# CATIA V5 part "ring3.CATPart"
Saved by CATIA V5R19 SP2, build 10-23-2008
Part number: ring3
Bounding box of the stored display mesh (mm): x 1208.801 to 1608.814, y 0 to 783.497, z 0 to 414.335
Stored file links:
  C:\BEHROOZ\catia learning\tarh haye mashin\hb\ring3.CATPart
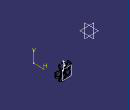
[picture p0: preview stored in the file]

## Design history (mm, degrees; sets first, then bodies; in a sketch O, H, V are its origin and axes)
Body1 (main body)
  Plane1: stored without definition
  DatumCurve1
  Line1: stored without definition
  Sketch1 on Plane1, origin (1402.6545, 0, 0), H (0, 1, 0), V (0, 0, 1)
    line L1 (763.5635, 414.3348) -> (783.4975, 338.6087)
    axis line L2 (763.5635, 208.175) -> (934.6232, 208.175)
    arc A1 centre (2119.5521, -103.7831) radius 1407.392 from (783.4975, 338.6087) to (747.1693, 208.175) ccw
    line L3 (747.1693, 208.175) -> (738.3224, 208.175)
    arc A2 centre (1438.5484, 90.6387) radius 710.022 from (738.3224, 208.175) to (762.752, 308.4239) cw
    line L4 (761.4882, 368.214) -> (744.4421, 414.3348)
    line L5 (744.4421, 414.3348) -> (763.5635, 414.3348)
    arc A3 centre (675.6576, 336.4913) radius 91.5053 from (762.752, 308.4239) to (761.4882, 368.214) ccw
  Shaft1: profile Sketch1, axis Line1, angle 360
  Plane2: stored without definition
  Plane3: type Offset, RefPlane Plane2, Offset 85
  Sketch2 on Plane3, origin (0, 841, 0), H (-1, 0, 0), V (0, 0, 1)
    construction line L1 (-1402.6545, 208.175) -> (-1196.4947, 208.175)
    construction line L2 (-1402.6545, 208.175) -> (-1338.9476, 404.2446)
    construction line L3 (-1402.6545, 208.175) -> (-1569.4414, 329.3527)
    construction line L4 (-1402.6545, 208.175) -> (-1569.4414, 86.9972)
    construction line L5 (-1402.6545, 208.175) -> (-1338.9476, 12.1053)
    axis line L6 through (-1402.6545, 208.175) direction (-0.309, 0.9511)
    line L7 (-1425.7363, 229.4708) -> (-1503.5268, 285.9888)
    arc A1 centre (-1282.5124, 371.6811) radius 238.7047 from (-1507.0557, 290.6859) to (-1521.217, 371.549) cw
    line L8 (-1396.4983, 238.9708) -> (-1366.785, 330.4189)
    arc A2 centre (-1595.9581, 269.8364) radius 238.7047 from (-1366.691, 336.2931) to (-1402.7643, 410.0366) ccw
    arc A3 centre (-1402.6545, 208.175) radius 190.3856 from (-1441.2397, 394.6095) to (-1481.022, 381.6835) ccw
    arc A4 centre (-1402.6545, 208.175) radius 206.1598 from (-1338.9476, 404.2446) to (-1411.276, 414.1545) ccw
    point P15 (-1338.9476, 404.2446)
    arc A5 centre (-1402.6545, 208.175) radius 206.1598 from (-1516.7514, 379.8834) to (-1569.4414, 329.3527) ccw
    point P16 (-1569.4414, 329.3527)
    arc A6 centre (-1201.2324, 325.4245) radius 294.2074 from (-1492.5962, 366.2304) to (-1495.1281, 311.8856) ccw
    arc A7 centre (-1246.5155, 716.3226) radius 483.7877 from (-1485.0087, 295.405) to (-1437.1395, 271.6732) ccw
    arc A8 centre (-1634.526, 184.6389) radius 294.2074 from (-1422.7928, 388.9108) to (-1388.8015, 346.4332) cw
    arc A9 centre (-1827.6553, 527.4988) radius 483.7877 from (-1387.3012, 327.1521) to (-1412.0789, 279.8159) cw
    arc A10 centre (-1511.217, 371.5545) radius 10 from (-1521.217, 371.549) to (-1516.7514, 379.8834) cw
    arc A11 centre (-1410.8578, 404.1632) radius 10 from (-1402.7643, 410.0366) to (-1411.276, 414.1545) ccw
    arc A12 centre (-1429.2591, 290.0552) radius 20 from (-1437.1395, 271.6732) to (-1412.0789, 279.8159) ccw
    arc A13 centre (-1405.5056, 335.4346) radius 20 from (-1387.3012, 327.1521) to (-1388.8015, 346.4332) ccw
    arc A14 centre (-1475.1493, 312.806) radius 20 from (-1485.0087, 295.405) to (-1495.1281, 311.8856) cw
    arc A15 centre (-1472.7895, 363.4564) radius 20 from (-1492.5962, 366.2304) to (-1481.022, 381.6835) cw
    arc A16 centre (-1437.1863, 375.0246) radius 20 from (-1441.2397, 394.6095) to (-1422.7928, 388.9108) cw
    arc A17 centre (-1376.2956, 333.5091) radius 10 from (-1366.785, 330.4189) to (-1366.691, 336.2931) ccw
    arc A18 centre (-1497.6489, 294.079) radius 10 from (-1503.5268, 285.9888) to (-1507.0557, 290.6859) cw
    point P48 (-1569.4414, 329.3527)
    point P49 (-1569.4414, 86.9972)
    point P51 (-1569.4414, 329.3527)
    point P52 (-1569.4414, 86.9972)
    line L9 (-1430.0407, 192.8036) -> (-1507.8312, 136.2856)
    arc A19 centre (-1521.0321, 372.9631) radius 238.7047 from (-1513.3888, 134.3809) to (-1594.6703, 145.9007) cw
    line L10 (-1430.0407, 223.5463) -> (-1507.8312, 280.0643)
    arc A20 centre (-1521.0321, 43.3868) radius 238.7047 from (-1513.3888, 281.969) to (-1594.6703, 270.4492) ccw
    arc A21 centre (-1402.6545, 208.175) radius 190.3856 from (-1591.8878, 229.0898) to (-1591.8878, 187.2602) ccw
    arc A22 centre (-1402.6545, 208.175) radius 206.1598 from (-1569.4414, 329.3527) to (-1601.2168, 263.6267) ccw
    arc A23 centre (-1402.6545, 208.175) radius 206.1598 from (-1601.2168, 152.7232) to (-1569.4414, 86.9972) ccw
    arc A24 centre (-1451.9226, 435.9709) radius 294.2074 from (-1580.7677, 171.4772) to (-1529.8651, 152.2757) ccw
    arc A25 centre (-1837.6821, 513.6982) radius 483.7877 from (-1511.0641, 156.8071) to (-1473.7014, 194.9998) ccw
    arc A26 centre (-1451.9226, -19.621) radius 294.2074 from (-1580.7677, 244.8727) to (-1529.8651, 264.0742) cw
    arc A27 centre (-1837.6821, -97.3483) radius 483.7877 from (-1511.0641, 259.5428) to (-1473.7014, 221.3501) cw
    arc A28 centre (-1591.5854, 155.413) radius 10 from (-1594.6703, 145.9007) to (-1601.2168, 152.7232) cw
    arc A29 centre (-1591.5854, 260.9369) radius 10 from (-1594.6703, 270.4492) to (-1601.2168, 263.6267) ccw
    arc A30 centre (-1488.7486, 208.175) radius 20 from (-1473.7014, 194.9998) to (-1473.7014, 221.3501) ccw
    arc A31 centre (-1524.5667, 244.7888) radius 20 from (-1511.0641, 259.5428) to (-1529.8651, 264.0742) ccw
    arc A32 centre (-1524.5667, 171.5611) radius 20 from (-1511.0641, 156.8071) to (-1529.8651, 152.2757) cw
    arc A33 centre (-1572.0089, 189.4573) radius 20 from (-1580.7677, 171.4772) to (-1591.8878, 187.2602) cw
    arc A34 centre (-1572.0089, 226.8927) radius 20 from (-1591.8878, 229.0898) to (-1580.7677, 244.8727) cw
    arc A35 centre (-1513.709, 271.9742) radius 10 from (-1507.8312, 280.0643) to (-1513.3888, 281.969) ccw
    arc A36 centre (-1513.709, 144.3757) radius 10 from (-1507.8312, 136.2856) to (-1513.3888, 134.3809) cw
    point P85 (-1569.4414, 86.9972)
    point P86 (-1338.9476, 12.1053)
    point P88 (-1569.4414, 86.9972)
    point P89 (-1338.9476, 12.1053)
    line L11 (-1396.4983, 177.3792) -> (-1366.785, 85.931)
    arc A37 centre (-1595.9581, 146.5135) radius 238.7047 from (-1366.691, 80.0568) to (-1402.7643, 6.3133) cw
    line L12 (-1425.7363, 186.8792) -> (-1503.5268, 130.3611)
    arc A38 centre (-1282.5124, 44.6688) radius 238.7047 from (-1507.0557, 125.664) to (-1521.217, 44.8009) ccw
    arc A39 centre (-1402.6545, 208.175) radius 190.3856 from (-1481.022, 34.6664) to (-1441.2397, 21.7404) ccw
    arc A40 centre (-1402.6545, 208.175) radius 206.1598 from (-1569.4414, 86.9972) to (-1516.7514, 36.4665) ccw
    arc A41 centre (-1402.6545, 208.175) radius 206.1598 from (-1411.276, 2.1955) to (-1338.9476, 12.1053) ccw
    arc A42 centre (-1634.526, 231.7111) radius 294.2074 from (-1422.7928, 27.4391) to (-1388.8015, 69.9167) ccw
    arc A43 centre (-1827.6553, -111.1489) radius 483.7877 from (-1387.3012, 89.1978) to (-1412.0789, 136.534) ccw
    arc A44 centre (-1201.2324, 90.9254) radius 294.2074 from (-1492.5962, 50.1196) to (-1495.1281, 104.4643) cw
    arc A45 centre (-1246.5155, -299.9727) radius 483.7877 from (-1485.0087, 120.9449) to (-1437.1395, 144.6767) cw
    arc A46 centre (-1410.8578, 12.1867) radius 10 from (-1402.7643, 6.3133) to (-1411.276, 2.1955) cw
    arc A47 centre (-1511.217, 44.7954) radius 10 from (-1521.217, 44.8009) to (-1516.7514, 36.4665) ccw
    arc A48 centre (-1429.2591, 126.2947) radius 20 from (-1412.0789, 136.534) to (-1437.1395, 144.6767) ccw
    arc A49 centre (-1475.1493, 103.5439) radius 20 from (-1485.0087, 120.9449) to (-1495.1281, 104.4643) ccw
    arc A50 centre (-1405.5056, 80.9154) radius 20 from (-1387.3012, 89.1978) to (-1388.8015, 69.9167) cw
    arc A51 centre (-1437.1863, 41.3253) radius 20 from (-1422.7928, 27.4391) to (-1441.2397, 21.7404) cw
    arc A52 centre (-1472.7895, 52.8935) radius 20 from (-1481.022, 34.6664) to (-1492.5962, 50.1196) cw
    arc A53 centre (-1497.6489, 122.2709) radius 10 from (-1503.5268, 130.3611) to (-1507.0557, 125.664) ccw
    arc A54 centre (-1376.2956, 82.8408) radius 10 from (-1366.785, 85.931) to (-1366.691, 80.0568) cw
    point P122 (-1338.9476, 12.1053)
    point P123 (-1196.4947, 208.175)
    point P125 (-1338.9476, 12.1053)
    point P126 (-1196.4947, 208.175)
    line L13 (-1371.4636, 204.5134) -> (-1275.3093, 204.5134)
    arc A55 centre (-1403.7451, 5.2779) radius 238.7047 from (-1269.6936, 202.7877) to (-1210.7067, 145.6919) cw
    line L14 (-1389.5337, 179.6421) -> (-1359.8204, 88.194)
    arc A56 centre (-1210.025, 271.9108) radius 238.7047 from (-1356.4437, 83.3863) to (-1283.9144, 44.93) ccw
    arc A57 centre (-1402.6545, 208.175) radius 190.3856 from (-1261.855, 80.026) to (-1237.2682, 113.8669) ccw
    arc A58 centre (-1402.6545, 208.175) radius 206.1598 from (-1338.9476, 12.1053) to (-1274.608, 46.6016) ccw
    arc A59 centre (-1402.6545, 208.175) radius 206.1598 from (-1209.4206, 136.3243) to (-1196.4947, 208.175) ccw
    arc A60 centre (-1496.6909, -5.0749) radius 294.2074 from (-1236.9876, 133.1718) to (-1266.8823, 178.6259) ccw
    arc A61 centre (-1230.292, -294.7013) radius 483.7877 from (-1284.7561, 186.0109) to (-1337.4322, 177.0735) ccw
    arc A62 centre (-1228.9008, 363.5067) radius 294.2074 from (-1280.1284, 73.7936) to (-1332.5958, 88.179) cw
    arc A63 centre (-871.1278, 199.6457) radius 483.7877 from (-1345.1426, 102.8959) to (-1352.9205, 155.7557) cw
    arc A64 centre (-1218.7936, 139.8095) radius 10 from (-1210.7067, 145.6919) to (-1209.4206, 136.3243) cw
    arc A65 centre (-1280.819, 54.4389) radius 10 from (-1283.9144, 44.93) to (-1274.608, 46.6016) ccw
    arc A66 centre (-1333.003, 157.5702) radius 20 from (-1337.4322, 177.0735) to (-1352.9205, 155.7557) ccw
    arc A67 centre (-1325.5466, 106.8956) radius 20 from (-1345.1426, 102.8959) to (-1332.5958, 88.179) ccw
    arc A68 centre (-1282.5045, 166.138) radius 20 from (-1284.7561, 186.0109) to (-1266.8823, 178.6259) cw
    arc A69 centre (-1254.642, 123.7739) radius 20 from (-1236.9876, 133.1718) to (-1237.2682, 113.8669) cw
    arc A70 centre (-1276.646, 93.488) radius 20 from (-1261.855, 80.026) to (-1280.1284, 73.7936) cw
    arc A71 centre (-1350.3098, 91.2841) radius 10 from (-1359.8204, 88.194) to (-1356.4437, 83.3863) ccw
    arc A72 centre (-1275.3093, 194.5134) radius 10 from (-1275.3093, 204.5134) to (-1269.6936, 202.7877) cw
    point P159 (-1196.4947, 208.175)
    point P160 (-1338.9476, 404.2446)
    point P162 (-1196.4947, 208.175)
    point P163 (-1338.9476, 404.2446)
    line L15 (-1389.5337, 236.7078) -> (-1359.8204, 328.156)
    arc A73 centre (-1210.025, 144.4391) radius 238.7047 from (-1356.4437, 332.9636) to (-1283.9144, 371.4199) cw
    line L16 (-1371.4636, 211.8365) -> (-1275.3093, 211.8365)
    arc A74 centre (-1403.7451, 411.072) radius 238.7047 from (-1269.6936, 213.5623) to (-1210.7067, 270.6581) ccw
    arc A75 centre (-1402.6545, 208.175) radius 190.3856 from (-1237.2682, 302.4831) to (-1261.855, 336.3239) ccw
    arc A76 centre (-1402.6545, 208.175) radius 206.1598 from (-1196.4947, 208.175) to (-1209.4206, 280.0256) ccw
    arc A77 centre (-1402.6545, 208.175) radius 206.1598 from (-1274.608, 369.7483) to (-1338.9476, 404.2446) ccw
    arc A78 centre (-1228.9008, 52.8432) radius 294.2074 from (-1280.1284, 342.5564) to (-1332.5958, 328.1709) ccw
    arc A79 centre (-871.1278, 216.7042) radius 483.7877 from (-1345.1426, 313.454) to (-1352.9205, 260.5942) ccw
    arc A80 centre (-1496.6909, 421.4248) radius 294.2074 from (-1236.9876, 283.1781) to (-1266.8823, 237.724) cw
    arc A81 centre (-1230.292, 711.0512) radius 483.7877 from (-1284.7561, 230.339) to (-1337.4322, 239.2764) cw
    arc A82 centre (-1280.819, 361.911) radius 10 from (-1283.9144, 371.4199) to (-1274.608, 369.7483) cw
    arc A83 centre (-1218.7936, 276.5404) radius 10 from (-1210.7067, 270.6581) to (-1209.4206, 280.0256) ccw
    arc A84 centre (-1333.003, 258.7798) radius 20 from (-1352.9205, 260.5942) to (-1337.4322, 239.2764) ccw
    arc A85 centre (-1282.5045, 250.2119) radius 20 from (-1284.7561, 230.339) to (-1266.8823, 237.724) ccw
    arc A86 centre (-1325.5466, 309.4543) radius 20 from (-1345.1426, 313.454) to (-1332.5958, 328.1709) cw
    arc A87 centre (-1276.646, 322.8619) radius 20 from (-1280.1284, 342.5564) to (-1261.855, 336.3239) cw
    arc A88 centre (-1254.642, 292.576) radius 20 from (-1237.2682, 302.4831) to (-1236.9876, 283.1781) cw
    arc A89 centre (-1275.3093, 221.8365) radius 10 from (-1275.3093, 211.8365) to (-1269.6936, 213.5623) ccw
    arc A90 centre (-1350.3098, 325.0658) radius 10 from (-1359.8204, 328.156) to (-1356.4437, 332.9636) cw
    arc A91 centre (-1414.5684, 244.8421) radius 19 from (-1396.4983, 238.9708) to (-1425.7363, 229.4708) cw
    arc A92 centre (-1371.4636, 230.8365) radius 19 from (-1389.5337, 236.7078) to (-1371.4636, 211.8365) ccw
    arc A93 centre (-1371.4636, 185.5134) radius 19 from (-1371.4636, 204.5134) to (-1389.5337, 179.6421) ccw
    arc A94 centre (-1414.5684, 171.5078) radius 19 from (-1425.7363, 186.8792) to (-1396.4983, 177.3792) cw
    arc A95 centre (-1441.2086, 208.175) radius 19 from (-1430.0407, 192.8036) to (-1430.0407, 223.5463) ccw
    coincidence: P15 P163, P16 P51, P52 P88, P89 P125, P126 P162
  Fillet1: radius 24, on edge [face of Shaft1 from Sketch1.L1 | face of Shaft1 from Sketch1.A1]
  Plane4: stored without definition
  Pocket1: profile Sketch2, direction (0, -1, 0), length 20, opposite side length -199
  Line2: stored without definition
  Sketch3 on Plane4, origin (1402.6545, 0, 0), H (0, 1, 0), V (0, 0, 1)
    line L1 (732.3534, 208.175) -> (743.964, 208.175)
    line L2 (743.964, 208.175) -> (759.5674, 269.8573)
    line L3 (759.5674, 269.8573) -> (751.5499, 269.9826)
    line L4 (751.5499, 269.9826) -> (732.3534, 208.175)
  Shaft2: profile Sketch3, axis Line2, angle 360
  Fillet2: radius 7, on edge [face of Pocket1 from Sketch2.L7 | face of Shaft2 from Sketch3.L3]; edge [face of Pocket1 from Sketch2.L15 | face of Shaft2 from Sketch3.L3]; edge [face of Pocket1 from Sketch2.L13 | face of Shaft2 from Sketch3.L3]; edge [face of Pocket1 from Sketch2.L11 | face of Shaft2 from Sketch3.L3]; edge [face of Pocket1 from Sketch2.L9 | face of Shaft2 from Sketch3.L3]
  Plane5: stored without definition
  Fillet3: radius 3, on edge [face of Shaft2 from Sketch3.L3 | face of Pocket1 from Sketch2.L8]; edge [face of Shaft2 from Sketch3.L3 | face of Pocket1 from Sketch2.L16]; edge [face of Shaft2 from Sketch3.L3 | face of Pocket1 from Sketch2.L14]; edge [face of Shaft2 from Sketch3.L3 | face of Pocket1 from Sketch2.L12]; edge [face of Shaft2 from Sketch3.L3 | face of Pocket1 from Sketch2.L10]
  Point1: stored without definition
  Sketch4 on Plane5, origin (0, 756, 0), H (-1, 0, 0), V (0, 0, 1)
    circle A1 centre (-1402.6545, 208.175) radius 17.8037
    line L1 (-1382.1496, 235.0632) -> (-1371.4307, 263.7447)
    line L2 (-1340.7259, 219.4906) -> (-1371.3449, 219.4906)
    arc A2 centre (-1371.3449, 231.0252) radius 11.5346 from (-1371.3449, 219.4906) to (-1382.1496, 235.0632) cw
    line L3 (-1421.8904, 235.9852) -> (-1445.8558, 255.0426)
    line L4 (-1394.2793, 270.5693) -> (-1403.7411, 241.449)
    arc A3 centre (-1414.7112, 245.0134) radius 11.5346 from (-1403.7411, 241.449) to (-1421.8904, 235.9852) cw
    line L5 (-1435.0479, 198.4744) -> (-1460.5782, 181.5711)
    line L6 (-1459.407, 235.4212) -> (-1434.6358, 217.4238)
    arc A4 centre (-1441.4156, 208.0921) radius 11.5346 from (-1434.6358, 217.4238) to (-1435.0479, 198.4744) cw
    line L7 (-1403.4389, 174.3694) -> (-1395.2521, 144.8652)
    line L8 (-1446.1047, 162.6197) -> (-1421.3335, 180.6171)
    arc A5 centre (-1414.5536, 171.2853) radius 11.5346 from (-1421.3335, 180.6171) to (-1403.4389, 174.3694) cw
    line L9 (-1370.7459, 196.9825) -> (-1340.1559, 195.6513)
    line L10 (-1372.7557, 152.774) -> (-1382.2175, 181.8944)
    arc A6 centre (-1371.2474, 185.4588) radius 11.5346 from (-1382.2175, 181.8944) to (-1370.7459, 196.9825) cw
    arc A7 centre (-1433.887, 308.7111) radius 54.9869 from (-1445.8558, 255.0426) to (-1394.2793, 270.5693) ccw
    arc A8 centre (-1507.9214, 209.5385) radius 54.9869 from (-1460.5782, 181.5711) to (-1459.407, 235.4212) ccw
    arc A9 centre (-1436.4806, 108.4816) radius 54.9869 from (-1395.2521, 144.8652) to (-1446.1047, 162.6197) ccw
    arc A10 centre (-1318.2933, 145.1975) radius 54.9869 from (-1340.1559, 195.6513) to (-1372.7557, 152.774) ccw
    arc A11 centre (-1316.6903, 268.9461) radius 54.9869 from (-1371.4307, 263.7447) to (-1340.7259, 219.4906) ccw
  Pocket2: profile Sketch4, direction (0, -1, 0), length 8, mirrored extent, thin wall 1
